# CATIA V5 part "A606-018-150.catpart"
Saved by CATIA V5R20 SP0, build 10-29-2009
Part number: A606-018-150
Source: Unknown
Property "ARTICLENO": "A606-018-150"
Property "BOMINFO": "A606-018-150"
Property "CODE": "A606-018-150"
Property "HOLES": "2"
Property "L": "150.000"
Property "L1": "25.000"
Property "L2": "100.000"
Property "LINA": "A606-018-150"
Property "NB": "A606-018-150"
Property "NBSYN": "$CODE."
Property "NN": "A606"
Property "NT": "Wear Plates, self-lubricating"
Property "SCREW": "2xM6"
Property "SUPPLIER": "CF"
Property "W": "18.000"
Bounding box of the stored display mesh (mm): x -9 to 9, y -5 to 5, z -75 to 75
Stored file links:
  C:\Users\Utente\Desktop\IO LAVORO\3D X SITO CF\A606 - Copia\A606-018-150\CATIAV5\A606-018-150.catpart
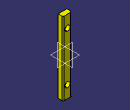
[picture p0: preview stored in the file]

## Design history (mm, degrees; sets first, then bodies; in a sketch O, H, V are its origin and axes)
Body1 "Geometry.1" (main body)
  Solid1 "A606-018-150.catpart": solid without history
